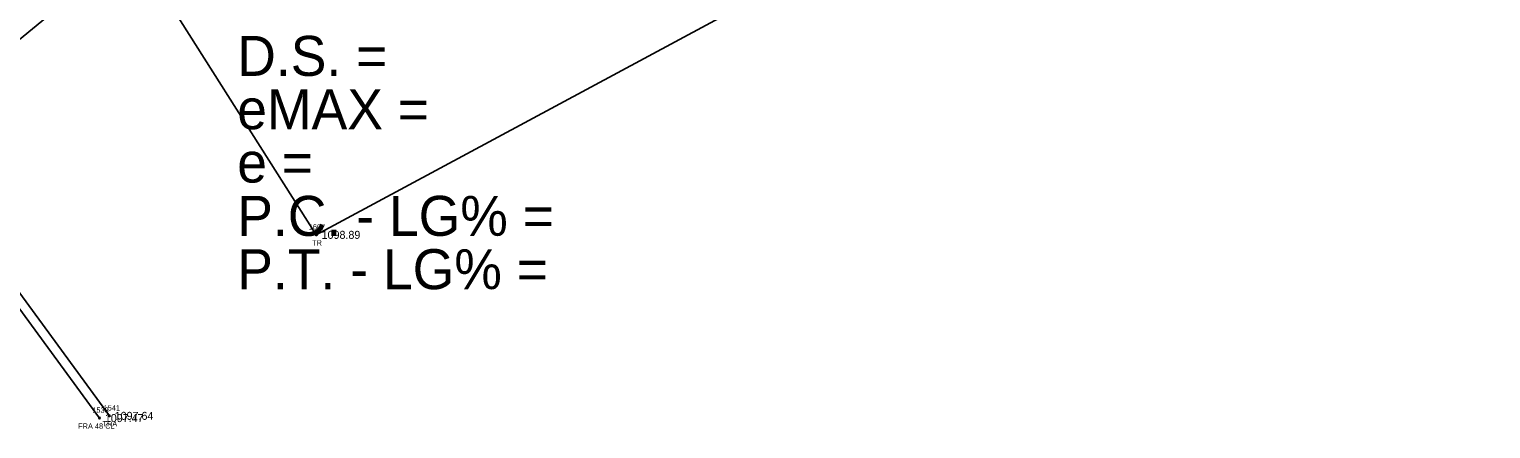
# Model space of a CAD drawing. Extents: x 1539151 to 1541799, y 1198646 to 1201165.
# Drawn here: x 1540955 to 1541228.9, y 1200187.8 to 1200262.8 of the extents above; entities that cross this region are included whole.
import ezdxf

# ---------------------------------------------------------------- set-up
doc = ezdxf.new("R2010")
doc.units = 0
for name, color, linetype in [('RD_EX_Fence_Other', 7, 'Continuous'), ('RD_EX_Fence_Other_txCode', 7, 'Continuous'), ('RD_EX_TX_Fence_Other_ELEV', 7, 'Continuous'), ('RD_EX_TX_VEG_ELEV', 7, 'Continuous'), ('RD_EX_VEG', 7, 'Continuous'), ('RD_EX_VEG_txCode', 7, 'Continuous'), ('RD_HC_Cl', 7, 'Continuous'), ('RD_HC_Data', 7, 'Continuous'), ('RD_SMD_Locator', 7, 'Continuous')]:
    doc.layers.add(name, color=color, linetype=linetype)

msp = doc.modelspace()

# ---------------------------------------------------------------- linework, layer by layer
at = {"layer": 'RD_EX_Fence_Other'}
msp.add_lwpolyline([(1540968.19, 1200189.83), (1540943.35, 1200223.76), (1540920.74, 1200254.84)], dxfattribs=at)
at = {"layer": 'RD_EX_VEG'}
msp.add_lwpolyline([(1540970.04, 1200190.25), (1540931.47, 1200242.98), (1540974.48, 1200278.36), (1541008.82, 1200224.19), (1541121.72, 1200285)], dxfattribs=at)
at = {"layer": 'RD_HC_Cl'}
msp.add_arc((1541347.27, 1199701.68), 731.44, 99.31232, 138.32753, dxfattribs=at)
at = {"layer": 'RD_SMD_Locator'}
for centre in [(1541008.82, 1200224.19), (1540968.19, 1200189.83), (1540970.04, 1200190.25)]:
    msp.add_circle(centre, 0.15, dxfattribs=at)

# ---------------------------------------------------------------- texts
at = {"layer": 'RD_EX_Fence_Other_txCode'}
for s, p in [('1538', (1540966.84, 1200190.83)), ('FRA 48 CL', (1540964.19, 1200187.83))]:
    msp.add_text(s, height=1, dxfattribs=at).set_placement(p)
at = {"layer": 'RD_EX_TX_Fence_Other_ELEV'}
msp.add_text('1097.47', height=1.5, dxfattribs=at).set_placement((1540969.19, 1200189.08))
at = {"layer": 'RD_EX_TX_VEG_ELEV'}
for s, p in [('1098.89', (1541009.82, 1200223.44)), ('1097.64', (1540971.04, 1200189.5))]:
    msp.add_text(s, height=1.5, dxfattribs=at).set_placement(p)
at = {"layer": 'RD_EX_VEG_txCode'}
for s, p in [('1607', (1541007.41, 1200225.19)), ('TR', (1541008.03, 1200222.19)), ('1541', (1540968.97, 1200191.25)), ('TRA', (1540968.75, 1200188.25))]:
    msp.add_text(s, height=1, dxfattribs=at).set_placement(p)
at = {"layer": 'RD_HC_Data'}
for s, p in [('D.S. = ', (1540994, 1200254)), ('eMAX = ', (1540994, 1200244)), ('e = ', (1540994, 1200234)), ('P.C. - LG% = ', (1540994, 1200224)), ('P.T. - LG% = ', (1540994, 1200214))]:
    msp.add_text(s, height=7.5, dxfattribs=at).set_placement(p)

doc.saveas('drawing.dxf')
